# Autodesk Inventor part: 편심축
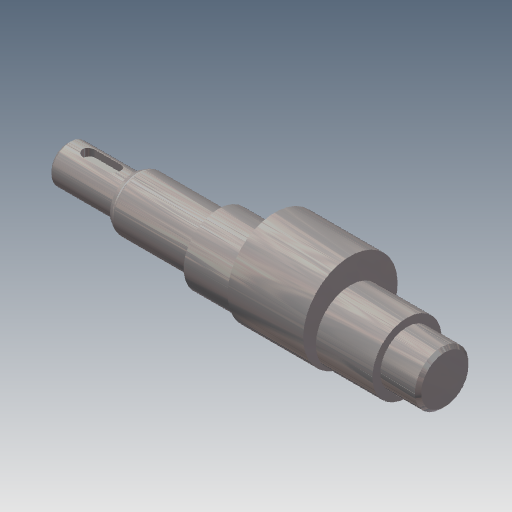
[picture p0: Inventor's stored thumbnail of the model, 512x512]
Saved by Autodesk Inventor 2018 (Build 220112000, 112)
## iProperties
Created: 2019-01
Part Number: 편심축
Material: 강철, 연강
Document SubType Name: Modeling
Designer: mduedu
Density: 7.86 g/cm^3
Appearance: 강철
Mass: 326.791 g
Surface Area: 90.982 cm^2
Volume: 41.5764 cm^3
Author: mduedu
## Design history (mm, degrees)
sketch "스케치1"
  geometry: L1 (0, 0)-(21, 0); L2 (21, 0)-(21, 6); L3 (21, 6)-(0, 6); L4 (0, 6)-(0, 0); L5 (21, 0)-(48, 0); L6 (48, 0)-(48, 8.5); L7 (48, 8.5)-(21, 8.5); L8 (21, 8.5)-(21, 0); L9 (48, 0)-(108, 0); L10 (108, 0)-(108, 11); L11 (108, 11)-(48, 11); L12 (48, 11)-(48, 0); L13 (108, 0)-(120, 0); L14 (120, 0)-(120, 8.5); L15 (120, 8.5)-(108, 8.5); L16 (108, 8.5)-(108, 0)
  constraints: 32 end point, 8 parallel, 4 horizontal, 4 perpendicular
  dimensions: "d0" = 120 distance between parallel lines of L14 L4; "d2" = 12 distance of L14.end L15.end; "d3" = 60 distance of L10.end L11.end; "d4" = 99 distance between parallel lines of L8 L14; "d5" = 12 diameter of L3 L1; "d6" = 17 diameter of L7 L5; "d7" = 17 diameter of L15 L13; "d8" = 22 diameter of L11 L9
revolve "회전1" sketch "스케치1" stored, may be unused: angle "d9" = 90 deg
node "작업 평면1"
sketch "스케치2"
  geometry: C1 r 15 at (0, 4); C2 r 11 at (0, 0) reference; 1 further point
  constraints: 1 centre point, 1 tangent, 1 vertical alignment
  dimensions: "d11" = 4 distance of point (0, 0) C1.centre
extrude "돌출1" join sketch "스케치2" distance "d12" = 24; taper "d13" = 0 deg
node "작업 평면2"
sketch "스케치3" dims "d16" = 12
  geometry: L1 (-4.5, 2)-(3.5, 2); L2 (3.5, 2)-(3.5, -2); L3 (3.5, -2)-(-4.5, -2); L4 (-4.5, -2)-(-4.5, 2); L5 (-10.5, 8.5)-(-10.5, -8.5) reference; 3 further points
  constraints: 8 end point, 2 midpoint, 2 parallel, 2 vertical alignment, 1 horizontal, 1 horizontal alignment, 1 perpendicular, 4 other
  dimensions: "d14" = 4 distance between parallel lines of L3 L1; "d17" = 4 dimension on L5
extrude "돌출2" cut sketch "스케치3" distance "d18" = 2.5; taper "d19" = 0 deg
chamfer "모따기1" distance "d20" = 1.82; stored, may be unused: second distance "d21" = 2, angle "d22" = 30 deg
fillet "모깎기1" dims "d23" = 2
hole "구멍2" diameter "d39" = 3.242; stored, may be unused: countersink angle "d43" = 60 deg, drill point angle "d45" = 118 deg; dims "d37" = 10, "d38" = 10, "d40" = 8, "d41" = 5.51, "d42" = 2, "d44" = 10
sketch "스케치5"
  geometry: L1 (0, 0)-(2, 0); L2 (2, 0)-(2, 1.621); L3 (0, 2.776)-(0, 0); L4 (0, 2.776)-(2, 1.621); L5 (10, 1.621)-(0, 1.621) reference
  constraints: 8 end point, 1 horizontal, 1 parallel, 1 perpendicular, 1 point on line
  dimensions: "d46" = 2 distance between parallel lines of L2 L3; "d48" = 30 deg angle of L4 L1
revolve "회전2" sketch "스케치5" stored, may be unused: angle "d50" = 90 deg
chamfer "모따기2" distance "d25" = 1; stored, may be unused: second distance "d26" = 2, angle "d27" = 30 deg
node "솔리드1"
